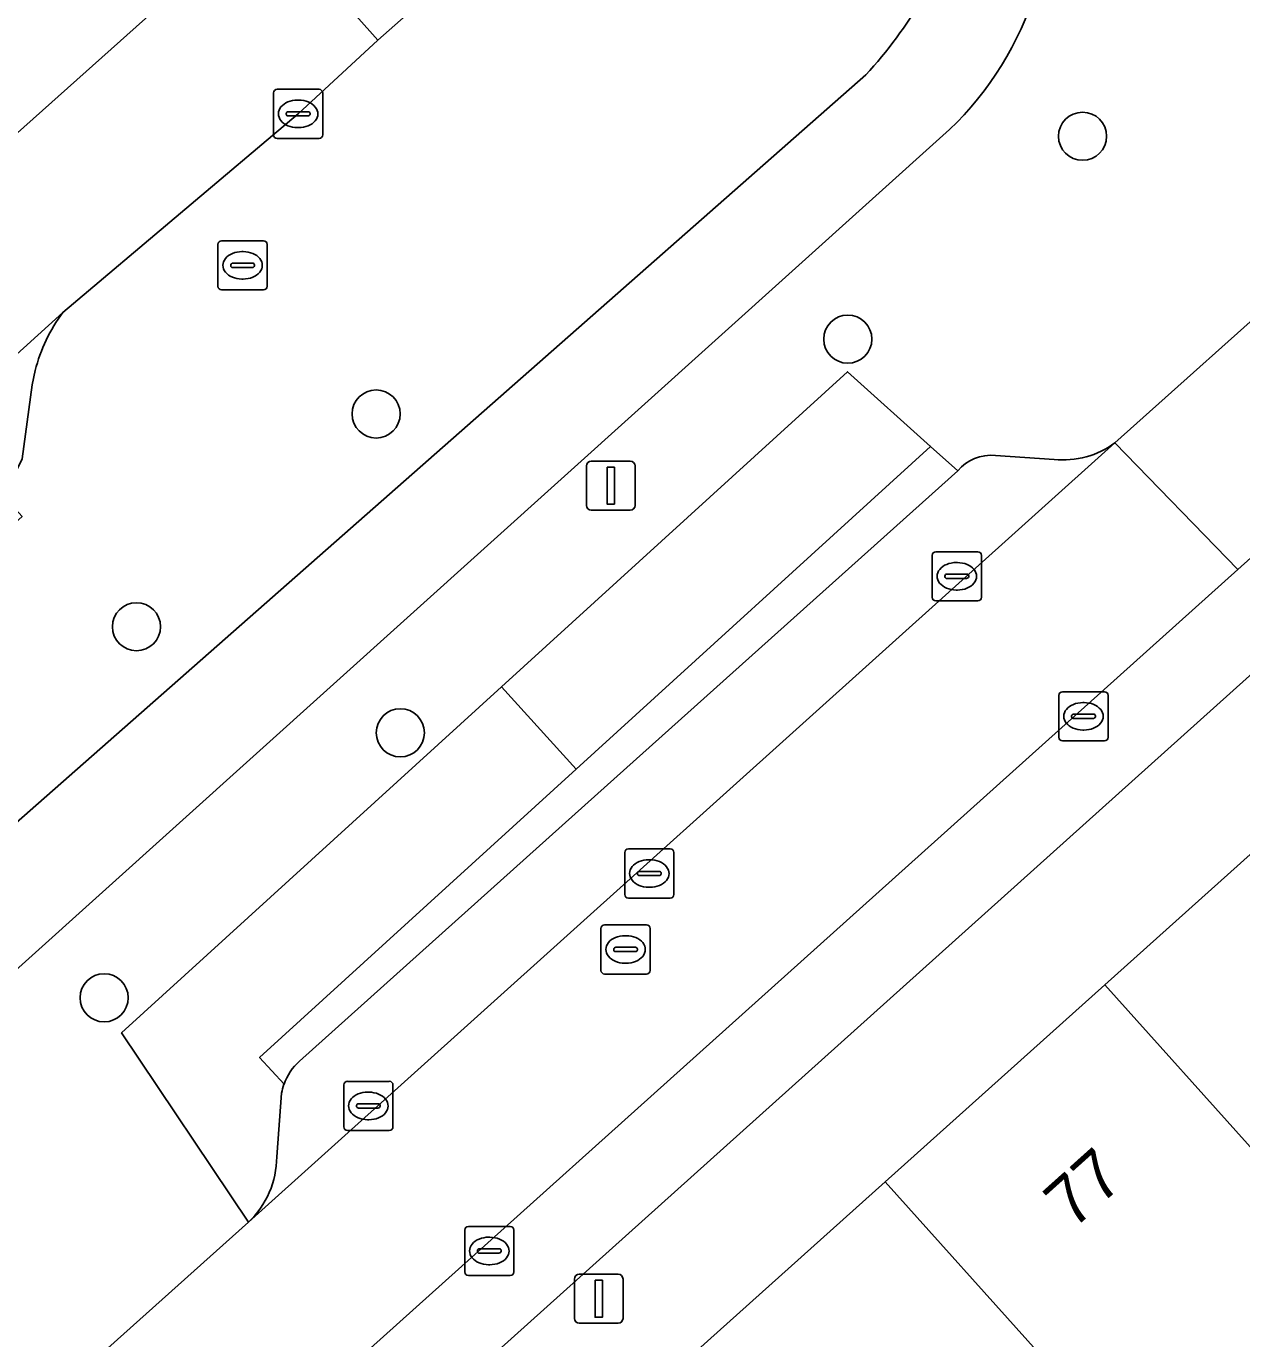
# Model space of a CAD drawing. Extents: x 162172 to 163187, y 382874 to 383685.
# Drawn here: x 162783.66 to 162808.38, y 383346.73 to 383373.42 of the extents above; entities that cross this region are included whole.
import ezdxf

# ---------------------------------------------------------------- set-up
doc = ezdxf.new("R2010")
doc.units = 0
for name, color, linetype in [('IMGEO_Berm_groen', 7, 'Continuous'), ('IMGEO_Boom', 7, 'Continuous'), ('IMGEO_Kolk', 7, 'Continuous'), ('IMGEO_Lichtmast', 7, 'Continuous'), ('IMGEO_Pand', 7, 'Continuous'), ('IMGEO_Pand_nummerreeks', 7, 'Continuous'), ('IMGEO_Parkeervlak_open', 7, 'Continuous'), ('IMGEO_Rijbaan_lokaal_open', 7, 'Continuous'), ('IMGEO_Rioolput', 7, 'Continuous'), ('IMGEO_Voetpad_halfverhard', 7, 'Continuous'), ('IMGEO_Voetpad_open', 7, 'Continuous')]:
    doc.layers.add(name, color=color, linetype=linetype)

msp = doc.modelspace()

# ---------------------------------------------------------------- linework, layer by layer
at = {"layer": 'IMGEO_Berm_groen'}
for points in [[(162795.363, 383377.17), (162794.445, 383376.349), (162790.812, 383373.137), (162789.192, 383371.636), (162784.406, 383367.598)], [(162805.798, 383364.945), (162809.569, 383368.324), (162817.637, 383375.567)], [(162775.641, 383350.343), (162800.736, 383372.427)], [(162802.438, 383371.316), (162777.312, 383348.702)], [(162744.611, 383310), (162750.185, 383314.921), (162765.945, 383329.187), (162788.183, 383349.104), (162785.604, 383352.953), (162793.329, 383359.988), (162800.361, 383366.393), (162802.051, 383364.873), (162802.602, 383364.378)], [(162783.844, 383366.416), (162783.781, 383366.125), (162783.581, 383364.62), (162783.236, 383363.917), (162783.193, 383363.878), (162783.578, 383363.446), (162777.815, 383358.239), (162770.993, 383352.074), (162770.569, 383352.558), (162770.529, 383352.523)], [(162803.369, 383364.689), (162804.563, 383364.61)], [(162794.844, 383358.31), (162793.329, 383359.988), (162785.604, 383352.953), (162788.183, 383349.104)], [(162788.905, 383351.905), (162788.409, 383352.45), (162794.844, 383358.31)], [(162788.756, 383350.428), (162788.856, 383351.722)]]:
    msp.add_lwpolyline(points, dxfattribs=at)
msp.add_lwpolyline([(162802.051, 383364.873), (162800.361, 383366.393), (162793.329, 383359.988), (162794.844, 383358.31)], close=True, dxfattribs=at)
for centre, radius, start, end in [((162793.849, 383378.698), 9.315, 317.6834, 329.7047), ((162797.773, 383376.165), 6.729, 313.8912, 342.5718), ((162787.163, 383365.563), 3.426, 143.5602, 165.5809), ((162804.756, 383366.343), 1.743, 263.6461, 306.707), ((162803.279, 383363.811), 0.883, 84.1262, 140.0165), ((162790.113, 383351.483), 1.28, 160.7655, 169.2548), ((162786.932, 383350.431), 1.824, 313.3011, 359.895)]:
    msp.add_arc(centre, radius, start, end, dxfattribs=at)
at = {"layer": 'IMGEO_Boom'}
for centre in [(162805.141, 383371.181), (162800.368, 383367.055), (162790.778, 383365.534), (162785.905, 383361.208), (162791.27, 383359.051), (162785.248, 383353.663)]:
    msp.add_circle(centre, 0.489, dxfattribs=at)
at = {"layer": 'IMGEO_Kolk'}
for p, q in [((162788.691, 383371.21), (162788.691, 383372.062)), ((162788.766, 383372.136), (162789.618, 383372.136)), ((162789.692, 383372.062), (162789.692, 383371.21)), ((162789.179, 383371.916), (162789.204, 383371.916)), ((162788.95, 383371.63), (162788.95, 383371.642)), ((162789.388, 383371.593), (162788.99, 383371.593)), ((162788.993, 383371.679), (162789.391, 383371.679)), ((162789.434, 383371.642), (162789.434, 383371.63)), ((162789.202, 383371.356), (162789.177, 383371.356)), ((162789.618, 383371.136), (162788.766, 383371.136)), ((162802.159, 383362.733), (162803.011, 383362.733)), ((162802.084, 383361.807), (162802.084, 383362.659)), ((162802.572, 383362.513), (162802.597, 383362.513)), ((162803.085, 383362.659), (162803.085, 383361.807)), ((162802.343, 383362.227), (162802.343, 383362.239)), ((162802.781, 383362.19), (162802.383, 383362.19)), ((162802.386, 383362.276), (162802.784, 383362.276)), ((162802.827, 383362.239), (162802.827, 383362.227)), ((162802.595, 383361.953), (162802.57, 383361.953)), ((162803.011, 383361.733), (162802.159, 383361.733)), ((162804.659, 383358.96), (162804.659, 383359.812)), ((162804.734, 383359.886), (162805.586, 383359.886)), ((162805.66, 383359.812), (162805.66, 383358.96)), ((162805.147, 383359.666), (162805.172, 383359.666)), ((162804.918, 383359.38), (162804.918, 383359.392)), ((162805.356, 383359.343), (162804.958, 383359.343)), ((162804.961, 383359.429), (162805.359, 383359.429)), ((162805.402, 383359.392), (162805.402, 383359.38)), ((162805.17, 383359.106), (162805.145, 383359.106)), ((162805.586, 383358.886), (162804.734, 383358.886)), ((162790.119, 383351.038), (162790.119, 383351.89)), ((162790.194, 383351.964), (162791.046, 383351.964)), ((162791.12, 383351.89), (162791.12, 383351.038)), ((162790.421, 383351.507), (162790.819, 383351.507)), ((162790.607, 383351.744), (162790.632, 383351.744)), ((162790.378, 383351.458), (162790.378, 383351.47)), ((162790.816, 383351.421), (162790.418, 383351.421)), ((162790.862, 383351.47), (162790.862, 383351.458)), ((162790.63, 383351.184), (162790.605, 383351.184)), ((162791.046, 383350.964), (162790.194, 383350.964)), ((162792.578, 383348.089), (162792.578, 383348.941)), ((162792.653, 383349.015), (162793.505, 383349.015)), ((162793.579, 383348.941), (162793.579, 383348.089)), ((162793.066, 383348.795), (162793.091, 383348.795)), ((162792.837, 383348.509), (162792.837, 383348.521)), ((162793.275, 383348.472), (162792.877, 383348.472)), ((162792.88, 383348.558), (162793.278, 383348.558)), ((162793.321, 383348.521), (162793.321, 383348.509)), ((162793.089, 383348.235), (162793.064, 383348.235)), ((162793.505, 383348.015), (162792.653, 383348.015))]:
    msp.add_line(p, q, dxfattribs=at)
for points in [[(162788.691, 383371.21), (162788.691, 383372.062)], [(162788.766, 383372.136), (162789.618, 383372.136)], [(162789.692, 383372.062), (162789.692, 383371.21)], [(162789.618, 383371.136), (162788.766, 383371.136)], [(162802.159, 383362.733), (162803.011, 383362.733)], [(162802.084, 383361.807), (162802.084, 383362.659)], [(162803.085, 383362.659), (162803.085, 383361.807)], [(162803.011, 383361.733), (162802.159, 383361.733)], [(162804.659, 383358.96), (162804.659, 383359.812)], [(162804.734, 383359.886), (162805.586, 383359.886)], [(162805.66, 383359.812), (162805.66, 383358.96)], [(162805.586, 383358.886), (162804.734, 383358.886)], [(162790.119, 383351.038), (162790.119, 383351.89)], [(162790.194, 383351.964), (162791.046, 383351.964)], [(162791.12, 383351.89), (162791.12, 383351.038)], [(162791.046, 383350.964), (162790.194, 383350.964)], [(162792.578, 383348.089), (162792.578, 383348.941)], [(162792.653, 383349.015), (162793.505, 383349.015)], [(162793.579, 383348.941), (162793.579, 383348.089)], [(162793.505, 383348.015), (162792.653, 383348.015)]]:
    msp.add_lwpolyline(points, dxfattribs=at)
for centre, radius, start, end in [((162788.768, 383372.06), 0.0765, 91.552, 178.448), ((162788.768, 383372.06), 0.0765, 91.552, 178.448), ((162789.616, 383372.06), 0.0765, 1.552, 88.448), ((162789.616, 383372.06), 0.0765, 1.552, 88.448), ((162788.99, 383371.639), 0.0403, 85.8775, 175.7526), ((162788.987, 383371.629), 0.0366, 178.938, 274.7102), ((162789.391, 383371.636), 0.043, 264.8664, 352.4533), ((162789.395, 383371.641), 0.0386, 1.7309, 96.639), ((162788.768, 383371.212), 0.0765, 181.552, 268.448), ((162788.768, 383371.212), 0.0765, 181.552, 268.448), ((162789.616, 383371.212), 0.0765, 271.552, 358.448), ((162789.616, 383371.212), 0.0765, 271.552, 358.448), ((162802.161, 383362.657), 0.0765, 91.552, 178.448), ((162802.161, 383362.657), 0.0765, 91.552, 178.448), ((162803.009, 383362.657), 0.0765, 1.552, 88.448), ((162803.009, 383362.657), 0.0765, 1.552, 88.448), ((162802.383, 383362.236), 0.0403, 85.8775, 175.7526), ((162802.38, 383362.226), 0.0366, 178.938, 274.7102), ((162802.784, 383362.233), 0.043, 264.8664, 352.4533), ((162802.788, 383362.238), 0.0386, 1.7309, 96.639), ((162802.161, 383361.809), 0.0765, 181.552, 268.448), ((162802.161, 383361.809), 0.0765, 181.552, 268.448), ((162803.009, 383361.809), 0.0765, 271.552, 358.448), ((162803.009, 383361.809), 0.0765, 271.552, 358.448), ((162804.736, 383359.81), 0.0765, 91.552, 178.448), ((162804.736, 383359.81), 0.0765, 91.552, 178.448), ((162805.584, 383359.81), 0.0765, 1.552, 88.448), ((162805.584, 383359.81), 0.0765, 1.552, 88.448), ((162804.958, 383359.389), 0.0403, 85.8775, 175.7526), ((162804.955, 383359.379), 0.0366, 178.938, 274.7102), ((162805.359, 383359.386), 0.043, 264.8664, 352.4533), ((162805.363, 383359.391), 0.0386, 1.7309, 96.639), ((162804.736, 383358.962), 0.0765, 181.552, 268.448), ((162804.736, 383358.962), 0.0765, 181.552, 268.448), ((162805.584, 383358.962), 0.0765, 271.552, 358.448), ((162805.584, 383358.962), 0.0765, 271.552, 358.448), ((162790.196, 383351.888), 0.0765, 91.552, 178.448), ((162790.196, 383351.888), 0.0765, 91.552, 178.448), ((162791.044, 383351.888), 0.0765, 1.552, 88.448), ((162791.044, 383351.888), 0.0765, 1.552, 88.448), ((162790.418, 383351.467), 0.0403, 85.8775, 175.7526), ((162790.823, 383351.469), 0.0386, 1.7309, 96.639), ((162790.415, 383351.457), 0.0366, 178.938, 274.7102), ((162790.819, 383351.464), 0.043, 264.8664, 352.4533), ((162790.196, 383351.04), 0.0765, 181.552, 268.448), ((162790.196, 383351.04), 0.0765, 181.552, 268.448), ((162791.044, 383351.04), 0.0765, 271.552, 358.448), ((162791.044, 383351.04), 0.0765, 271.552, 358.448), ((162792.655, 383348.939), 0.0765, 91.552, 178.448), ((162792.655, 383348.939), 0.0765, 91.552, 178.448), ((162793.503, 383348.939), 0.0765, 1.552, 88.448), ((162793.503, 383348.939), 0.0765, 1.552, 88.448), ((162792.877, 383348.518), 0.0403, 85.8775, 175.7526), ((162792.874, 383348.508), 0.0366, 178.938, 274.7102), ((162793.278, 383348.515), 0.043, 264.8664, 352.4533), ((162793.282, 383348.52), 0.0386, 1.7309, 96.639), ((162792.655, 383348.091), 0.0765, 181.552, 268.448), ((162792.655, 383348.091), 0.0765, 181.552, 268.448), ((162793.503, 383348.091), 0.0765, 271.552, 358.448), ((162793.503, 383348.091), 0.0765, 271.552, 358.448)]:
    msp.add_arc(centre, radius, start, end, dxfattribs=at)
for centre, major_axis, ratio, start_param, end_param in [((162789.178, 383371.636), (-0.387, 0.002), 0.722429, 4.712389, 7.853982), ((162789.203, 383371.636), (-0.39, 0.002), 0.717154, 1.570796, 4.712389), ((162802.571, 383362.233), (-0.387, 0.002), 0.722429, 4.712389, 7.853982), ((162802.596, 383362.233), (-0.39, 0.002), 0.717154, 1.570796, 4.712389), ((162805.146, 383359.386), (-0.387, 0.002), 0.722429, 4.712389, 7.853982), ((162805.171, 383359.386), (-0.39, 0.002), 0.717154, 1.570796, 4.712389), ((162790.606, 383351.464), (-0.387, 0.002), 0.722429, 4.712389, 7.853982), ((162790.631, 383351.464), (-0.39, 0.002), 0.717154, 1.570796, 4.712389), ((162793.065, 383348.515), (-0.387, 0.002), 0.722429, 4.712389, 7.853982), ((162793.09, 383348.515), (-0.39, 0.002), 0.717154, 1.570796, 4.712389)]:
    msp.add_ellipse(centre, major_axis=major_axis, ratio=ratio, start_param=start_param, end_param=end_param, dxfattribs=at)
at = {"layer": 'IMGEO_Lichtmast'}
for p, q in [((162795.053, 383363.676), (162795.053, 383364.476)), ((162795.053, 383364.476), (162795.053, 383363.676)), ((162795.153, 383364.576), (162795.943, 383364.576)), ((162795.943, 383364.576), (162795.153, 383364.576)), ((162796.043, 383364.476), (162796.043, 383363.676)), ((162796.043, 383363.676), (162796.043, 383364.476)), ((162795.943, 383363.576), (162795.153, 383363.576)), ((162795.153, 383363.576), (162795.943, 383363.576)), ((162794.908, 383348.044), (162795.698, 383348.044)), ((162795.698, 383348.044), (162794.908, 383348.044)), ((162794.808, 383347.144), (162794.808, 383347.944)), ((162794.808, 383347.944), (162794.808, 383347.144)), ((162795.798, 383347.944), (162795.798, 383347.144)), ((162795.798, 383347.144), (162795.798, 383347.944)), ((162795.698, 383347.044), (162794.908, 383347.044)), ((162794.908, 383347.044), (162795.698, 383347.044))]:
    msp.add_line(p, q, dxfattribs=at)
for points in [[(162795.473, 383364.451), (162795.623, 383364.451), (162795.623, 383363.701), (162795.473, 383363.701), (162795.473, 383364.451)], [(162795.228, 383347.919), (162795.378, 383347.919), (162795.378, 383347.169), (162795.228, 383347.169), (162795.228, 383347.919)]]:
    msp.add_lwpolyline(points, dxfattribs=at)
for centre, start, end in [((162795.153, 383364.476), 90, 180), ((162795.153, 383364.476), 90, 180), ((162795.943, 383364.476), 0, 90), ((162795.943, 383364.476), 360, 90), ((162795.153, 383363.676), 180, 270), ((162795.153, 383363.676), 180, 270), ((162795.943, 383363.676), 270, 0), ((162795.943, 383363.676), 270, 0), ((162794.908, 383347.944), 90, 180), ((162794.908, 383347.944), 90, 180), ((162795.698, 383347.944), 0, 90), ((162795.698, 383347.944), 360, 90), ((162794.908, 383347.144), 180, 270), ((162794.908, 383347.144), 180, 270), ((162795.698, 383347.144), 270, 0), ((162795.698, 383347.144), 270, 0)]:
    msp.add_arc(centre, 0.1, start, end, dxfattribs=at)
at = {"layer": 'IMGEO_Pand'}
for points in [[(162810.063, 383357.934), (162805.597, 383353.928), (162811.869, 383346.935), (162816.335, 383350.942)], [(162811.869, 383346.935), (162805.597, 383353.928), (162801.13, 383349.921), (162807.403, 383342.928)], [(162807.403, 383342.928), (162801.13, 383349.921), (162796.664, 383345.915), (162802.937, 383338.921)]]:
    msp.add_lwpolyline(points, close=True, dxfattribs=at)
at = {"layer": 'IMGEO_Parkeervlak_open'}
for points in [[(162736.538, 383329.17), (162736.903, 383329.498), (162763.169, 383353.106), (162788.501, 383375.734), (162792.101, 383379), (162829.073, 383412.003)], [(162843.693, 383394.145), (162811.886, 383365.593), (162808.297, 383362.372), (162752.534, 383312.314), (162752.272, 383312.079), (162752.63, 383312.208), (162753.767, 383312.366), (162754.785, 383312.353)], [(162755.461, 383312.558), (162842.607, 383390.811)], [(162784.406, 383367.598), (162767.014, 383351.829)], [(162783.193, 383363.878), (162783.236, 383363.917), (162783.581, 383364.62), (162783.781, 383366.125), (162783.844, 383366.416)], [(162788.183, 383349.104), (162805.798, 383364.945)], [(162804.563, 383364.61), (162803.369, 383364.689)], [(162802.602, 383364.378), (162795.288, 383357.818), (162789.217, 383352.373)], [(162788.856, 383351.722), (162788.756, 383350.428)]]:
    msp.add_lwpolyline(points, dxfattribs=at)
for centre, radius, start, end in [((162787.163, 383365.563), 3.426, 143.5602, 165.5809), ((162804.756, 383366.343), 1.743, 263.6461, 306.707), ((162803.279, 383363.811), 0.883, 84.1262, 140.0165), ((162790.004, 383351.51), 1.168, 132.3759, 160.244), ((162790.113, 383351.483), 1.28, 160.7655, 169.2548), ((162786.932, 383350.431), 1.824, 313.3011, 359.895)]:
    msp.add_arc(centre, radius, start, end, dxfattribs=at)
at = {"layer": 'IMGEO_Rijbaan_lokaal_open'}
for points in [[(162790.812, 383373.137), (162794.445, 383376.349), (162792.101, 383379), (162788.501, 383375.734)], [(162765.744, 383350.688), (162767.014, 383351.829), (162784.406, 383367.598), (162789.192, 383371.636), (162790.812, 383373.137), (162788.501, 383375.734), (162763.169, 383353.106), (162736.903, 383329.498), (162739.256, 383327.009), (162745.187, 383332.231), (162745.503, 383332.515), (162749.865, 383336.431), (162759.725, 383345.284), (162762.702, 383347.957)], [(162811.886, 383365.593), (162809.569, 383368.324), (162805.798, 383364.945), (162808.297, 383362.372)], [(162752.534, 383312.314), (162808.297, 383362.372), (162805.798, 383364.945), (162788.183, 383349.104), (162765.945, 383329.187), (162750.185, 383314.921)]]:
    msp.add_lwpolyline(points, close=True, dxfattribs=at)
at = {"layer": 'IMGEO_Rioolput'}
for p, q in [((162787.562, 383368.13), (162787.562, 383368.982)), ((162787.637, 383369.056), (162788.489, 383369.056)), ((162788.563, 383368.982), (162788.563, 383368.13)), ((162787.864, 383368.599), (162788.262, 383368.599)), ((162788.05, 383368.836), (162788.075, 383368.836)), ((162787.821, 383368.55), (162787.821, 383368.562)), ((162788.259, 383368.513), (162787.861, 383368.513)), ((162788.305, 383368.562), (162788.305, 383368.55)), ((162788.489, 383368.056), (162787.637, 383368.056)), ((162788.073, 383368.276), (162788.048, 383368.276)), ((162795.832, 383355.764), (162795.832, 383356.616)), ((162795.907, 383356.69), (162796.759, 383356.69)), ((162796.833, 383356.616), (162796.833, 383355.764)), ((162796.32, 383356.47), (162796.345, 383356.47)), ((162796.091, 383356.184), (162796.091, 383356.196)), ((162796.529, 383356.147), (162796.131, 383356.147)), ((162796.134, 383356.233), (162796.532, 383356.233)), ((162796.575, 383356.196), (162796.575, 383356.184)), ((162796.343, 383355.91), (162796.318, 383355.91)), ((162796.759, 383355.69), (162795.907, 383355.69)), ((162795.349, 383354.22), (162795.349, 383355.072)), ((162795.424, 383355.146), (162796.276, 383355.146)), ((162796.35, 383355.072), (162796.35, 383354.22)), ((162795.837, 383354.926), (162795.862, 383354.926)), ((162795.608, 383354.64), (162795.608, 383354.652)), ((162796.046, 383354.603), (162795.648, 383354.603)), ((162795.651, 383354.689), (162796.049, 383354.689)), ((162796.092, 383354.652), (162796.092, 383354.64)), ((162795.86, 383354.366), (162795.835, 383354.366)), ((162796.276, 383354.146), (162795.424, 383354.146))]:
    msp.add_line(p, q, dxfattribs=at)
for points in [[(162787.562, 383368.13), (162787.562, 383368.982)], [(162787.637, 383369.056), (162788.489, 383369.056)], [(162788.563, 383368.982), (162788.563, 383368.13)], [(162788.489, 383368.056), (162787.637, 383368.056)], [(162795.832, 383355.764), (162795.832, 383356.616)], [(162795.907, 383356.69), (162796.759, 383356.69)], [(162796.833, 383356.616), (162796.833, 383355.764)], [(162796.759, 383355.69), (162795.907, 383355.69)], [(162795.349, 383354.22), (162795.349, 383355.072)], [(162795.424, 383355.146), (162796.276, 383355.146)], [(162796.35, 383355.072), (162796.35, 383354.22)], [(162796.276, 383354.146), (162795.424, 383354.146)]]:
    msp.add_lwpolyline(points, dxfattribs=at)
for centre, radius, start, end in [((162787.639, 383368.98), 0.0765, 91.552, 178.448), ((162787.639, 383368.98), 0.0765, 91.552, 178.448), ((162788.487, 383368.98), 0.0765, 1.552, 88.448), ((162788.487, 383368.98), 0.0765, 1.552, 88.448), ((162787.861, 383368.559), 0.0403, 85.8775, 175.7526), ((162788.266, 383368.561), 0.0386, 1.7309, 96.639), ((162787.858, 383368.549), 0.0366, 178.938, 274.7102), ((162788.262, 383368.556), 0.043, 264.8664, 352.4533), ((162787.639, 383368.132), 0.0765, 181.552, 268.448), ((162787.639, 383368.132), 0.0765, 181.552, 268.448), ((162788.487, 383368.132), 0.0765, 271.552, 358.448), ((162788.487, 383368.132), 0.0765, 271.552, 358.448), ((162795.909, 383356.614), 0.0765, 91.552, 178.448), ((162795.909, 383356.614), 0.0765, 91.552, 178.448), ((162796.757, 383356.614), 0.0765, 1.552, 88.448), ((162796.757, 383356.614), 0.0765, 1.552, 88.448), ((162796.131, 383356.193), 0.0403, 85.8775, 175.7526), ((162796.128, 383356.183), 0.0366, 178.938, 274.7102), ((162796.532, 383356.19), 0.043, 264.8664, 352.4533), ((162796.536, 383356.195), 0.0386, 1.7309, 96.639), ((162795.909, 383355.766), 0.0765, 181.552, 268.448), ((162795.909, 383355.766), 0.0765, 181.552, 268.448), ((162796.757, 383355.766), 0.0765, 271.552, 358.448), ((162796.757, 383355.766), 0.0765, 271.552, 358.448), ((162795.426, 383355.07), 0.0765, 91.552, 178.448), ((162795.426, 383355.07), 0.0765, 91.552, 178.448), ((162796.274, 383355.07), 0.0765, 1.552, 88.448), ((162796.274, 383355.07), 0.0765, 1.552, 88.448), ((162795.648, 383354.649), 0.0403, 85.8775, 175.7526), ((162795.645, 383354.639), 0.0366, 178.938, 274.7102), ((162796.049, 383354.646), 0.043, 264.8664, 352.4533), ((162796.053, 383354.651), 0.0386, 1.7309, 96.639), ((162795.426, 383354.222), 0.0765, 181.552, 268.448), ((162795.426, 383354.222), 0.0765, 181.552, 268.448), ((162796.274, 383354.222), 0.0765, 271.552, 358.448), ((162796.274, 383354.222), 0.0765, 271.552, 358.448)]:
    msp.add_arc(centre, radius, start, end, dxfattribs=at)
for centre, major_axis, ratio, start_param, end_param in [((162788.049, 383368.556), (-0.387, 0.002), 0.722429, 4.712389, 7.853982), ((162788.074, 383368.556), (-0.39, 0.002), 0.717154, 1.570796, 4.712389), ((162796.319, 383356.19), (-0.387, 0.002), 0.722429, 4.712389, 7.853982), ((162796.344, 383356.19), (-0.39, 0.002), 0.717154, 1.570796, 4.712389), ((162795.836, 383354.646), (-0.387, 0.002), 0.722429, 4.712389, 7.853982), ((162795.861, 383354.646), (-0.39, 0.002), 0.717154, 1.570796, 4.712389)]:
    msp.add_ellipse(centre, major_axis=major_axis, ratio=ratio, start_param=start_param, end_param=end_param, dxfattribs=at)
at = {"layer": 'IMGEO_Voetpad_halfverhard'}
for points in [[(162800.736, 383372.427), (162775.641, 383350.343)], [(162777.312, 383348.702), (162802.438, 383371.316)]]:
    msp.add_lwpolyline(points, dxfattribs=at)
for centre, radius, start, end in [((162793.849, 383378.698), 9.315, 317.6834, 329.7047), ((162797.773, 383376.165), 6.729, 313.8912, 342.5718)]:
    msp.add_arc(centre, radius, start, end, dxfattribs=at)
at = {"layer": 'IMGEO_Voetpad_open'}
for points in [[(162842.607, 383390.811), (162755.461, 383312.558)], [(162802.602, 383364.378), (162802.051, 383364.873), (162794.844, 383358.31), (162788.409, 383352.45), (162788.905, 383351.905)], [(162789.217, 383352.373), (162795.288, 383357.818), (162802.602, 383364.378)], [(162763.413, 383316.169), (162766.792, 383319.195), (162770.039, 383322.104), (162773.633, 383325.324), (162778.081, 383329.309), (162782.641, 383333.394), (162783.75, 383334.333), (162788.4, 383338.504), (162792.867, 383342.51), (162796.664, 383345.915), (162801.13, 383349.921), (162805.597, 383353.928), (162810.063, 383357.934)]]:
    msp.add_lwpolyline(points, dxfattribs=at)
msp.add_arc((162790.004, 383351.51), 1.168, 132.3759, 160.244, dxfattribs=at)

# ---------------------------------------------------------------- texts
at = {"layer": 'IMGEO_Pand_nummerreeks'}
msp.add_text('77', height=1, rotation=41.8897, dxfattribs=at).set_placement((162804.94, 383348.933))

doc.saveas('drawing.dxf')
